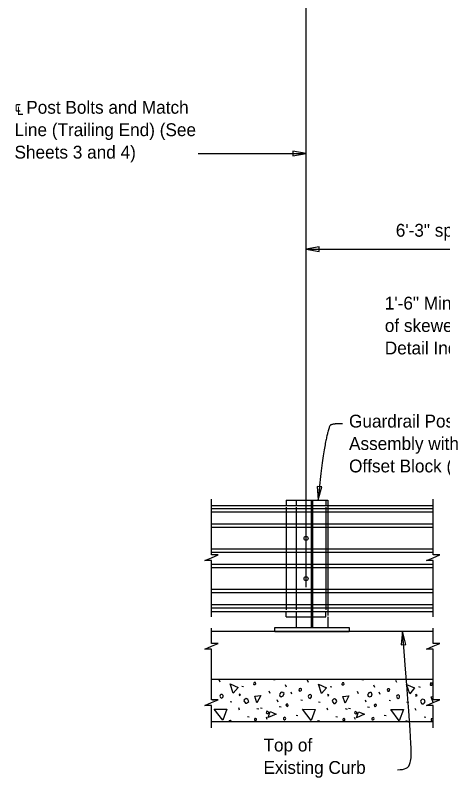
# Model space of a CAD drawing. Extents: x 21516.9 to 21586.2, y 56154.4 to 56193.6.
# Drawn here: x 21518.15 to 21524.85, y 56169.67 to 56181.64 of the extents above; entities that cross this region are included whole.
import ezdxf

# ---------------------------------------------------------------- set-up
doc = ezdxf.new("R2010")
doc.units = 0
for name, color, linetype in [('AdhocPoint_dp', 7, 'Continuous'), ('Border', 7, 'Continuous'), ('Patterning', 7, 'Continuous'), ('PlotBorder_dp', 7, 'Continuous'), ('SheetBorder_dp', 7, 'Continuous'), ('TextMisc', 7, 'Continuous')]:
    doc.layers.add(name, color=color, linetype=linetype)

msp = doc.modelspace()

# ---------------------------------------------------------------- linework, layer by layer
at = {"layer": 'AdhocPoint_dp'}
for p, q in [((21524.703, 56171.97), (21521.226, 56171.97)), ((21521.226, 56171.22), (21524.703, 56171.22)), ((21524.703, 56170.553), (21521.226, 56170.553))]:
    msp.add_line(p, q, dxfattribs=at)
at = {"layer": 'Border'}
for p, q in [((21522.792, 56172.032), (21522.792, 56174.032)), ((21522.813, 56172.032), (21522.813, 56174.032)), ((21523.053, 56174.032), (21523.053, 56172.219)), ((21522.553, 56173.921), (21522.553, 56172.309))]:
    msp.add_line(p, q, dxfattribs=at)
at = {"layer": 'Patterning'}
for p, q in [((21522.396, 56174.032), (21523.021, 56174.032)), ((21522.396, 56174.032), (21522.396, 56173.949)), ((21523.021, 56174.032), (21523.021, 56173.949)), ((21522.396, 56173.921), (21522.396, 56172.309)), ((21523.021, 56173.921), (21523.021, 56172.309)), ((21522.396, 56172.199), (21522.396, 56172.282)), ((21523.021, 56172.199), (21523.021, 56172.282)), ((21522.396, 56172.199), (21523.021, 56172.199)), ((21521.361, 56171.175), (21521.347, 56171.21)), ((21522.746, 56171.171), (21522.732, 56171.207)), ((21524.131, 56171.168), (21524.117, 56171.203)), ((21521.702, 56171.112), (21521.73, 56171.105)), ((21522.4, 56171.097), (21522.386, 56171.132)), ((21523.087, 56171.109), (21523.115, 56171.102)), ((21523.785, 56171.093), (21523.771, 56171.128)), ((21524.471, 56171.105), (21524.5, 56171.098)), ((21522.144, 56170.996), (21522.13, 56171.031)), ((21522.488, 56170.984), (21522.474, 56171.019)), ((21523.529, 56170.992), (21523.514, 56171.028)), ((21523.873, 56170.98), (21523.858, 56171.016)), ((21521.241, 56170.899), (21521.266, 56170.896)), ((21521.517, 56170.871), (21521.547, 56170.866)), ((21522.269, 56170.863), (21522.257, 56170.897)), ((21522.626, 56170.896), (21522.651, 56170.892)), ((21522.902, 56170.867), (21522.932, 56170.862)), ((21523.654, 56170.86), (21523.642, 56170.893)), ((21524.011, 56170.892), (21524.035, 56170.889)), ((21524.286, 56170.864), (21524.316, 56170.858)), ((21521.665, 56170.737), (21521.653, 56170.77)), ((21521.939, 56170.763), (21521.968, 56170.756)), ((21521.992, 56170.773), (21522.02, 56170.766)), ((21522.288, 56170.791), (21522.318, 56170.786)), ((21523.05, 56170.733), (21523.038, 56170.767)), ((21523.324, 56170.759), (21523.352, 56170.752)), ((21523.377, 56170.769), (21523.405, 56170.762)), ((21523.673, 56170.788), (21523.703, 56170.782)), ((21524.435, 56170.729), (21524.422, 56170.763)), ((21521.793, 56170.638), (21521.819, 56170.632)), ((21522.098, 56170.59), (21522.086, 56170.624)), ((21522.552, 56170.659), (21522.578, 56170.653)), ((21523.177, 56170.634), (21523.204, 56170.629)), ((21523.483, 56170.587), (21523.47, 56170.62)), ((21523.936, 56170.655), (21523.963, 56170.65)), ((21524.562, 56170.63), (21524.589, 56170.625))]:
    msp.add_line(p, q, dxfattribs=at)
for points in [[(21521.889, 56171.137), (21521.911, 56171.137), (21521.921, 56171.148), (21521.916, 56171.167), (21521.893, 56171.169), (21521.889, 56171.158), (21521.884, 56171.15), (21521.889, 56171.137), (21521.886, 56171.141)], [(21522.2, 56171.22), (21522.2, 56171.218), (21522.222, 56171.215), (21522.224, 56171.22)], [(21523.274, 56171.134), (21523.295, 56171.134), (21523.306, 56171.144), (21523.3, 56171.164), (21523.278, 56171.165), (21523.274, 56171.155), (21523.269, 56171.146), (21523.274, 56171.134), (21523.27, 56171.137)], [(21523.582, 56171.22), (21523.585, 56171.215), (21523.606, 56171.211), (21523.611, 56171.22)], [(21524.659, 56171.13), (21524.68, 56171.13), (21524.69, 56171.141), (21524.685, 56171.16), (21524.662, 56171.162), (21524.659, 56171.151), (21524.653, 56171.142), (21524.659, 56171.13), (21524.655, 56171.134)], [(21521.565, 56171), (21521.517, 56171.147), (21521.642, 56171.092), (21521.565, 56171)], [(21522.598, 56171.051), (21522.606, 56171.035), (21522.626, 56171.037), (21522.635, 56171.049), (21522.636, 56171.069), (21522.624, 56171.074), (21522.615, 56171.076), (21522.605, 56171.072), (21522.601, 56171.069), (21522.598, 56171.051)], [(21522.949, 56170.996), (21522.902, 56171.143), (21523.027, 56171.088), (21522.949, 56170.996)], [(21523.982, 56171.048), (21523.991, 56171.032), (21524.011, 56171.033), (21524.019, 56171.046), (21524.021, 56171.065), (21524.009, 56171.071), (21524, 56171.072), (21523.989, 56171.069), (21523.986, 56171.065), (21523.982, 56171.048)], [(21524.334, 56170.993), (21524.286, 56171.14), (21524.412, 56171.085), (21524.334, 56170.993)], [(21521.358, 56170.956), (21521.368, 56170.934), (21521.386, 56170.924), (21521.4, 56170.934), (21521.407, 56170.945), (21521.407, 56170.966), (21521.391, 56170.982), (21521.372, 56170.98), (21521.363, 56170.972), (21521.358, 56170.956)], [(21521.664, 56170.965), (21521.683, 56170.973), (21521.676, 56170.98), (21521.664, 56170.986), (21521.658, 56170.973), (21521.664, 56170.965)], [(21521.937, 56170.849), (21521.903, 56170.953), (21521.997, 56170.966), (21521.937, 56170.849)], [(21522.298, 56170.959), (21522.321, 56170.946), (21522.351, 56170.959), (21522.363, 56170.996), (21522.345, 56171.013), (21522.322, 56171.019), (21522.312, 56171.012), (21522.299, 56170.992), (21522.291, 56170.976), (21522.298, 56170.959)], [(21522.743, 56170.952), (21522.753, 56170.931), (21522.771, 56170.92), (21522.785, 56170.931), (21522.792, 56170.942), (21522.792, 56170.963), (21522.776, 56170.979), (21522.757, 56170.977), (21522.748, 56170.968), (21522.743, 56170.952)], [(21523.048, 56170.961), (21523.068, 56170.97), (21523.061, 56170.977), (21523.048, 56170.982), (21523.043, 56170.97), (21523.048, 56170.961)], [(21523.322, 56170.845), (21523.288, 56170.95), (21523.382, 56170.962), (21523.322, 56170.845)], [(21523.682, 56170.955), (21523.705, 56170.943), (21523.735, 56170.955), (21523.748, 56170.992), (21523.73, 56171.01), (21523.707, 56171.015), (21523.696, 56171.008), (21523.684, 56170.989), (21523.675, 56170.973), (21523.682, 56170.955)], [(21524.127, 56170.949), (21524.138, 56170.927), (21524.155, 56170.917), (21524.17, 56170.927), (21524.177, 56170.938), (21524.177, 56170.959), (21524.161, 56170.975), (21524.141, 56170.973), (21524.132, 56170.965), (21524.127, 56170.949)], [(21524.433, 56170.957), (21524.452, 56170.966), (21524.445, 56170.973), (21524.433, 56170.979), (21524.428, 56170.966), (21524.433, 56170.957)], [(21524.703, 56170.853), (21524.673, 56170.946), (21524.703, 56170.95)], [(21521.734, 56170.88), (21521.757, 56170.843), (21521.78, 56170.844), (21521.789, 56170.853), (21521.809, 56170.873), (21521.796, 56170.903), (21521.771, 56170.917), (21521.754, 56170.91), (21521.74, 56170.896), (21521.734, 56170.88)], [(21522.4, 56170.804), (21522.41, 56170.793), (21522.421, 56170.8), (21522.428, 56170.811), (21522.424, 56170.828), (21522.415, 56170.83), (21522.403, 56170.828), (21522.392, 56170.818), (21522.4, 56170.804)], [(21523.119, 56170.876), (21523.142, 56170.839), (21523.165, 56170.841), (21523.174, 56170.85), (21523.193, 56170.869), (21523.181, 56170.899), (21523.156, 56170.913), (21523.138, 56170.906), (21523.124, 56170.892), (21523.119, 56170.876)], [(21523.784, 56170.8), (21523.795, 56170.79), (21523.805, 56170.797), (21523.813, 56170.807), (21523.809, 56170.825), (21523.8, 56170.827), (21523.788, 56170.825), (21523.777, 56170.814), (21523.784, 56170.8)], [(21524.504, 56170.873), (21524.527, 56170.835), (21524.55, 56170.837), (21524.559, 56170.846), (21524.578, 56170.866), (21524.566, 56170.896), (21524.541, 56170.91), (21524.523, 56170.903), (21524.509, 56170.889), (21524.504, 56170.873)], [(21521.402, 56170.576), (21521.268, 56170.752), (21521.467, 56170.751), (21521.402, 56170.576)], [(21522.094, 56170.685), (21522.107, 56170.683), (21522.119, 56170.688), (21522.123, 56170.699), (21522.117, 56170.708), (21522.107, 56170.715), (21522.094, 56170.72), (21522.087, 56170.706), (21522.084, 56170.695), (21522.094, 56170.685)], [(21522.117, 56170.62), (21522.145, 56170.712), (21522.239, 56170.675), (21522.117, 56170.62)], [(21522.787, 56170.572), (21522.652, 56170.749), (21522.852, 56170.747), (21522.787, 56170.572)], [(21523.479, 56170.681), (21523.491, 56170.679), (21523.504, 56170.685), (21523.507, 56170.695), (21523.502, 56170.704), (21523.491, 56170.711), (21523.479, 56170.716), (21523.472, 56170.702), (21523.468, 56170.692), (21523.479, 56170.681)], [(21523.501, 56170.616), (21523.53, 56170.708), (21523.623, 56170.671), (21523.501, 56170.616)], [(21524.171, 56170.569), (21524.037, 56170.745), (21524.237, 56170.744), (21524.171, 56170.569)], [(21521.543, 56170.553), (21521.543, 56170.554), (21521.535, 56170.563), (21521.519, 56170.572), (21521.503, 56170.567), (21521.498, 56170.553)], [(21521.901, 56170.579), (21521.92, 56170.574), (21521.932, 56170.583), (21521.934, 56170.595), (21521.931, 56170.599), (21521.916, 56170.606), (21521.904, 56170.604), (21521.902, 56170.592), (21521.901, 56170.579)], [(21522.364, 56170.584), (21522.371, 56170.584), (21522.385, 56170.592), (21522.391, 56170.607), (21522.389, 56170.616), (21522.375, 56170.623), (21522.357, 56170.613), (21522.354, 56170.602), (21522.357, 56170.592), (21522.364, 56170.584)], [(21522.926, 56170.553), (21522.919, 56170.56), (21522.903, 56170.569), (21522.887, 56170.563), (21522.884, 56170.553)], [(21523.285, 56170.576), (21523.305, 56170.57), (21523.317, 56170.579), (21523.319, 56170.592), (21523.315, 56170.595), (21523.301, 56170.602), (21523.289, 56170.6), (21523.287, 56170.588), (21523.285, 56170.576)], [(21523.749, 56170.581), (21523.756, 56170.581), (21523.77, 56170.588), (21523.775, 56170.604), (21523.774, 56170.613), (21523.759, 56170.62), (21523.742, 56170.609), (21523.738, 56170.599), (21523.742, 56170.588), (21523.749, 56170.581)], [(21524.307, 56170.553), (21524.304, 56170.556), (21524.288, 56170.565), (21524.272, 56170.56), (21524.27, 56170.553)], [(21524.703, 56170.589), (21524.7, 56170.592), (21524.686, 56170.599), (21524.673, 56170.597), (21524.672, 56170.584), (21524.67, 56170.572)], [(21524.67, 56170.572), (21524.689, 56170.567), (21524.702, 56170.576), (21524.703, 56170.583)]]:
    msp.add_lwpolyline(points, dxfattribs=at)
at = {"layer": 'PlotBorder_dp'}
msp.add_line((21522.709, 56172.666), (21522.709, 56187.009), dxfattribs=at)
for points in [[(21522.709, 56179.471), (21522.501, 56179.506), (21522.501, 56179.436)], [(21522.709, 56177.97), (21522.917, 56177.935), (21522.917, 56178.005)], [(21522.898, 56174.034), (21522.954, 56174.238), (21522.884, 56174.245)], [(21524.219, 56171.973), (21524.202, 56171.762), (21524.272, 56171.768)]]:
    msp.add_lwpolyline(points, close=True, dxfattribs=at)
for points in [[(21522.709, 56177.97), (21528.84, 56177.97), (21528.84, 56178.073), (21528.885, 56177.97), (21528.93, 56177.867), (21528.93, 56177.97), (21534.896, 56177.97)], [(21521.226, 56172.199), (21521.226, 56173.083), (21521.123, 56173.083), (21521.226, 56173.128), (21521.329, 56173.173), (21521.226, 56173.173), (21521.226, 56174.045)], [(21524.703, 56172.199), (21524.703, 56173.083), (21524.599, 56173.083), (21524.703, 56173.128), (21524.806, 56173.173), (21524.703, 56173.173), (21524.703, 56174.045)], [(21521.226, 56171.222), (21521.226, 56171.693), (21521.123, 56171.693), (21521.226, 56171.738), (21521.329, 56171.783), (21521.226, 56171.783), (21521.226, 56172.02)], [(21524.703, 56171.222), (21524.703, 56171.693), (21524.599, 56171.693), (21524.703, 56171.738), (21524.806, 56171.783), (21524.703, 56171.783), (21524.703, 56172.02)], [(21521.226, 56170.457), (21521.226, 56170.808), (21521.123, 56170.808), (21521.226, 56170.853), (21521.329, 56170.898), (21521.226, 56170.898), (21521.226, 56171.222)], [(21524.703, 56170.457), (21524.703, 56170.808), (21524.599, 56170.808), (21524.703, 56170.853), (21524.806, 56170.898), (21524.703, 56170.898), (21524.703, 56171.222)]]:
    msp.add_lwpolyline(points, dxfattribs=at)
for points, degree in [([(21523.278, 56175.231), (21523.114, 56175.231), (21523.062, 56175.178), (21522.964, 56174.691), (21522.898, 56174.034)], 2), ([(21524.144, 56169.801), (21524.265, 56169.803), (21524.37, 56169.833), (21524.37, 56170.193), (21524.219, 56171.973)], 3)]:
    msp.add_open_spline(points, degree=degree, dxfattribs=at)
at = {"layer": 'SheetBorder_dp'}
msp.add_line((21521.017, 56179.471), (21522.709, 56179.471), dxfattribs=at)
at = {"layer": 'TextMisc'}
for p, q in [((21522.553, 56174.032), (21523.053, 56174.032)), ((21522.553, 56174.032), (21522.553, 56173.949)), ((21521.226, 56173.949), (21524.703, 56173.949)), ((21524.703, 56173.893), (21521.226, 56173.893)), ((21524.703, 56173.845), (21521.226, 56173.845)), ((21524.703, 56173.652), (21521.226, 56173.652)), ((21524.703, 56173.604), (21521.226, 56173.604)), ((21524.703, 56173.26), (21521.226, 56173.26)), ((21524.703, 56173.212), (21521.226, 56173.212)), ((21524.703, 56173.019), (21521.226, 56173.019)), ((21524.703, 56172.971), (21521.226, 56172.971)), ((21524.703, 56172.627), (21521.226, 56172.627)), ((21524.703, 56172.579), (21521.226, 56172.579)), ((21524.703, 56172.386), (21521.226, 56172.386)), ((21524.703, 56172.338), (21521.226, 56172.338)), ((21521.226, 56172.282), (21524.703, 56172.282)), ((21522.553, 56172.282), (21522.553, 56172.032)), ((21523.053, 56172.199), (21523.053, 56172.032)), ((21522.219, 56172.032), (21523.386, 56172.032)), ((21522.219, 56171.97), (21522.219, 56172.032)), ((21522.553, 56172.032), (21523.053, 56172.032)), ((21523.386, 56172.032), (21523.386, 56171.97)), ((21522.219, 56171.97), (21523.386, 56171.97))]:
    msp.add_line(p, q, dxfattribs=at)
for centre in [(21522.709, 56173.432), (21522.709, 56172.799)]:
    msp.add_circle(centre, 0.0312, dxfattribs=at)

# ---------------------------------------------------------------- texts
at = {"layer": 'PlotBorder_dp'}
for s, p in [('℄ Post Bolts and Match ', (21518.136, 56180.096)), ('Line (Trailing End) (See ', (21518.136, 56179.744)), ('Sheets 3 and 4)', (21518.136, 56179.392)), ('1\'-6" Min. for non skewed joints.  For treatment', (21523.944, 56177.023)), ('of skewed Intermediate Deck Joints see Skew ', (21523.944, 56176.671)), ('Detail Index 460-470, Sheet 2 (Typ.)', (21523.944, 56176.319)), ('Guardrail Post ', (21523.383, 56175.171)), ('Assembly with ', (21523.383, 56174.819)), ('Offset Block (Typ.)', (21523.383, 56174.467)), ('Top of ', (21522.041, 56170.087)), ('Existing Curb', (21522.041, 56169.735))]:
    msp.add_text(s, height=0.2016, dxfattribs=at).set_placement(p)
at = {"layer": 'SheetBorder_dp'}
msp.add_text('6\'-3" spacing (Typ. except as noted along Bridge, see Note 2)', height=0.2016, dxfattribs=at).set_placement((21524.116, 56178.166))

doc.saveas('drawing.dxf')
